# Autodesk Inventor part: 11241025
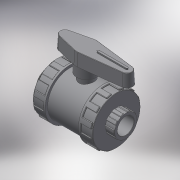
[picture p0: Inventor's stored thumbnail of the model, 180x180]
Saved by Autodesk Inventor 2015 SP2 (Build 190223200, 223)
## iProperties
Created: 2017-11
Part Number: 11241025
Material: Generic
Description: PLASSON BI STOPALVE THR PVC 2.1/2"
Document SubType Name: Modeling
Designer: KIM
Density: 1 g/cm^3
Appearance: Default
Author: KIM
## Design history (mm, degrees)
derived "112410 - 112710.ipt"
feature "Solid1::112410 - 112710.ipt"
tag "TaggingFeature1"
body "Solid1"
other parameters: "d0" = 215, "d1" = 72.226, "d2" = 139, "d3" = 44, "d4" = 57.7808, "d5" = 30.8, "d7" = 101.1164, "d8" = 125.1, "d13" = 2.16678, "d23" = 44, "d24" = 133.44, "d25" = 1.44452, "d26" = 2.16678, "d27" = 20.85, "d28" = 10.425, "d29" = 33, "d30" = 0, "d35" = 2.16678, "d39" = 69.5, "d45" = 360 deg, "d47" = 1.44452, "d50" = 76.45, "d51" = 41.7, "d53" = 0, "d55" = 14.4452, "d56" = 7.2226, "d57" = 30.8, "d58" = 0, "d59" = 2.16678, "d61" = 360 deg, "d63" = 55.6, "d64" = 128, "d66" = 132, "d68" = 27.8, "d69" = 39.6, "d70" = 32, "d71" = 3 deg, "d73" = 2.78, "d74" = 52.8, "d75" = 3.84, "d76" = 0, "d77" = 1.44452, "G_" = 72.226, "l_" = 44, "H_" = 215, "K_" = 139, "F_" = 128, "J_" = 132, "d67" = 55.6, "d72" = 13.9
